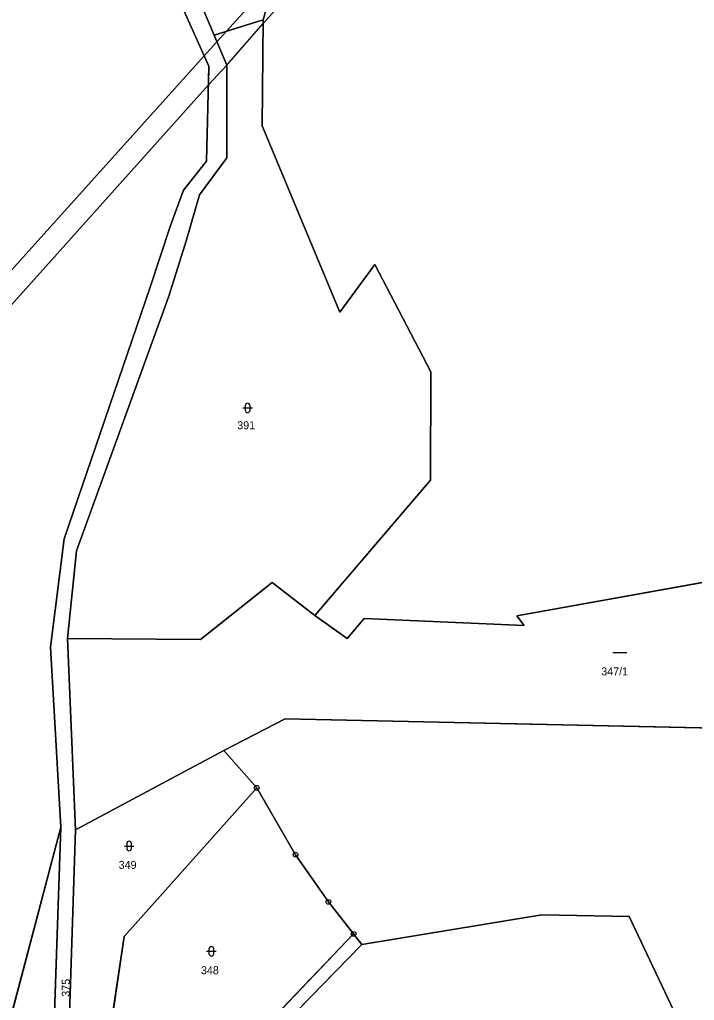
# Model space of a CAD drawing. Extents: x -689422 to -685210, y -987725 to -982160.
# Drawn here: x -686725.1 to -686581.7, y -987064.7 to -986856.4 of the extents above; entities that cross this region are included whole.
import ezdxf

# ---------------------------------------------------------------- set-up
doc = ezdxf.new("R2010")
doc.units = 0
for name, color, linetype in [('KN_Hranice_parcel', 7, 'Continuous'), ('KN_Parcelni cisla', 7, 'Continuous'), ('KN_Polygon parcely', 7, 'Continuous'), ('KN_POZEMKY_LESNI POZEMEK', 7, 'Continuous'), ('KN_POZEMKY_ORNA PUDA', 7, 'Continuous'), ('KN_POZEMKY_OSTATNI PLOCHA', 7, 'Continuous'), ('KN_POZEMKY_TTP', 7, 'Continuous'), ('KN_POZEMKY_VODNI_PLOCHA', 7, 'Continuous'), ('KN_VYUZITI_11_vodni plocha_zamokrena plocha', 7, 'Continuous'), ('KN_VYUZITI_27_ostatni plocha_neplodna puda', 7, 'Continuous'), ('KN_Věcná břemena k části', 7, 'Continuous'), ('KN_Značky bodu BP', 7, 'Continuous'), ('KN_Značky kultur', 7, 'Continuous')]:
    doc.layers.add(name, color=color, linetype=linetype)

msp = doc.modelspace()

# ---------------------------------------------------------------- linework, layer by layer
at = {"layer": 'KN_Hranice_parcel'}
for p, q in [((-686683.77, -986859.67), (-686687.52, -986850.74)), ((-686683.77, -986859.67), (-686673.32, -986856.41)), ((-686681.09, -986866.04), (-686683.77, -986859.67)), ((-686713.26, -987028.49), (-686714.94, -986987.85)), ((-686681.69, -987011.66), (-686713.26, -987028.49)), ((-686681.69, -987011.66), (-686674.7, -987019.58)), ((-686733.52, -987092.86), (-686716.4, -987027.91)), ((-686713.26, -987028.49), (-686714.49, -987067.68)), ((-686690.67, -987088.77), (-686654.13, -987050.63)), ((-686654.13, -987050.63), (-686652.37, -987052.87)), ((-686688.62, -987090), (-686652.37, -987052.87))]:
    msp.add_line(p, q, dxfattribs=at)
for points in [[(-686673.32, -986856.41), (-686666.27, -986831.41), (-686664.05, -986828.32)], [(-686691.17, -986852.38), (-686684.89, -986866.29), (-686685.39, -986886.42), (-686690.27, -986892.63), (-686693.02, -986900.13), (-686697.36, -986913.18), (-686715.65, -986966.67), (-686718.56, -986989.73), (-686716.4, -987027.91)], [(-686662.38, -986982.96), (-686637.77, -986954.19), (-686637.74, -986931.17), (-686649.58, -986908.38), (-686657.04, -986918.52), (-686673.53, -986878.97), (-686673.32, -986856.41)], [(-686714.94, -986987.85), (-686713.04, -986969.23), (-686693.39, -986915.11), (-686689.62, -986903.15), (-686686.9, -986893.59), (-686681.09, -986885.71), (-686681.09, -986866.04)], [(-686662.38, -986982.96), (-686655.5, -986987.84), (-686651.87, -986983.58), (-686617.9, -986985.1), (-686619.46, -986983.03), (-686557.32, -986971.9), (-686505.91, -986947.47)], [(-686504.67, -986950.08), (-686560.93, -987007.24), (-686668.7, -987004.92), (-686681.69, -987011.66)], [(-686714.94, -986987.85), (-686686.65, -986988.06), (-686671.44, -986975.93), (-686662.38, -986982.96)], [(-686674.7, -987019.58), (-686702.89, -987051.19), (-686706.43, -987074.82)], [(-686674.7, -987019.58), (-686666.47, -987033.78), (-686659.49, -987043.8), (-686654.13, -987050.63)], [(-686716.4, -987027.91), (-686717.94, -987073.53), (-686728.06, -987101.24)], [(-686652.37, -987052.87), (-686614.11, -987046.56), (-686595.53, -987046.88), (-686581.68, -987076.21)]]:
    msp.add_lwpolyline(points, dxfattribs=at)
at = {"layer": 'KN_Polygon parcely'}
for points in [[(-686733.52, -987092.86), (-686716.4, -987027.91), (-686718.56, -986989.73), (-686715.65, -986966.67), (-686697.36, -986913.18), (-686693.02, -986900.13), (-686690.27, -986892.63), (-686685.39, -986886.42), (-686684.89, -986866.29), (-686691.17, -986852.38), (-686681.76, -986829.17), (-686675.53, -986783.03), (-686669.76, -986751.7), (-686668.93, -986748.08), (-686678.49, -986747.97), (-686683.49, -986747.92), (-686683.45, -986743.82), (-686687.59, -986743.78), (-686689.2, -986743.77), (-686703.89, -986756.61), (-686709.75, -986769.81), (-686726.31, -986778.54)], [(-686666.27, -986831.41), (-686673.32, -986856.41), (-686673.53, -986878.97), (-686657.04, -986918.52), (-686649.58, -986908.38), (-686637.74, -986931.17), (-686637.77, -986954.19), (-686662.38, -986982.96), (-686655.5, -986987.84), (-686651.87, -986983.58), (-686617.9, -986985.1), (-686619.46, -986983.03), (-686557.32, -986971.9), (-686505.91, -986947.47), (-686469.15, -986930), (-686412.17, -986912.77), (-686386.41, -986874.65), (-686371.81, -986852.38)], [(-686691.17, -986852.38), (-686684.89, -986866.29), (-686685.39, -986886.42), (-686690.27, -986892.63), (-686693.02, -986900.13), (-686697.36, -986913.18), (-686715.65, -986966.67), (-686718.56, -986989.73), (-686716.4, -987027.91), (-686717.94, -987073.53)], [(-686714.49, -987067.68), (-686713.26, -987028.49), (-686714.94, -986987.85), (-686713.04, -986969.23), (-686693.39, -986915.11), (-686689.62, -986903.15), (-686686.9, -986893.59), (-686681.09, -986885.71), (-686681.09, -986866.04), (-686683.77, -986859.67), (-686687.52, -986850.74)]]:
    msp.add_lwpolyline(points, dxfattribs=at)
for points in [[(-686673.32, -986856.41), (-686666.27, -986831.41), (-686664.05, -986828.32), (-686667.8, -986817.71), (-686679.02, -986830.76), (-686687.52, -986850.74), (-686683.77, -986859.67)], [(-686637.74, -986931.17), (-686649.58, -986908.38), (-686657.04, -986918.52), (-686673.53, -986878.97), (-686673.32, -986856.41), (-686683.77, -986859.67), (-686681.09, -986866.04), (-686681.09, -986885.71), (-686686.9, -986893.59), (-686689.62, -986903.15), (-686693.39, -986915.11), (-686713.04, -986969.23), (-686714.94, -986987.85), (-686686.65, -986988.06), (-686671.44, -986975.93), (-686662.38, -986982.96), (-686637.77, -986954.19)], [(-686652.37, -987052.87), (-686614.11, -987046.56), (-686595.53, -987046.88), (-686581.68, -987076.21), (-686572.33, -987071.03), (-686546.33, -987062.48), (-686523.93, -987050.98), (-686517.25, -987045.2), (-686492.74, -987035.48), (-686491.96, -987039.41), (-686473.83, -987019.69), (-686459.48, -986999.8), (-686446.86, -986992.75), (-686438.2, -986975.26), (-686433.86, -986944.85), (-686451.29, -986938.63), (-686504.67, -986950.08), (-686560.93, -987007.24), (-686668.7, -987004.92), (-686681.69, -987011.66), (-686674.7, -987019.58), (-686666.47, -987033.78), (-686659.49, -987043.8), (-686654.13, -987050.63)], [(-686505.91, -986947.47), (-686557.32, -986971.9), (-686619.46, -986983.03), (-686617.9, -986985.1), (-686651.87, -986983.58), (-686655.5, -986987.84), (-686662.38, -986982.96), (-686671.44, -986975.93), (-686686.65, -986988.06), (-686714.94, -986987.85), (-686713.26, -987028.49), (-686681.69, -987011.66), (-686668.7, -987004.92), (-686560.93, -987007.24), (-686504.67, -986950.08)], [(-686713.26, -987028.49), (-686714.49, -987067.68), (-686706.43, -987074.82), (-686702.89, -987051.19), (-686674.7, -987019.58), (-686681.69, -987011.66)], [(-686702.89, -987051.19), (-686706.43, -987074.82), (-686690.67, -987088.77), (-686654.13, -987050.63), (-686659.49, -987043.8), (-686666.47, -987033.78), (-686674.7, -987019.58)], [(-686716.4, -987027.91), (-686733.52, -987092.86), (-686728.06, -987101.24), (-686717.94, -987073.53)], [(-686574.05, -987105.43), (-686575.15, -987097.93), (-686581.68, -987076.21), (-686595.53, -987046.88), (-686614.11, -987046.56), (-686652.37, -987052.87), (-686688.62, -987090), (-686617.02, -987138.1), (-686603.14, -987129.29)], [(-686688.62, -987090), (-686652.37, -987052.87), (-686654.13, -987050.63), (-686690.67, -987088.77)]]:
    msp.add_lwpolyline(points, close=True, dxfattribs=at)
at = {"layer": 'KN_POZEMKY_LESNI POZEMEK'}
for p, q in [((-686666.27, -986831.41), (-686673.32, -986856.41)), ((-686683.77, -986859.67), (-686687.52, -986850.74)), ((-686673.32, -986856.41), (-686683.77, -986859.67))]:
    msp.add_line(p, q, dxfattribs=at)
at = {"layer": 'KN_POZEMKY_ORNA PUDA'}
for p, q in [((-686673.32, -986856.41), (-686666.27, -986831.41)), ((-686673.53, -986878.97), (-686673.32, -986856.41)), ((-686657.04, -986918.52), (-686673.53, -986878.97)), ((-686649.58, -986908.38), (-686657.04, -986918.52)), ((-686637.74, -986931.17), (-686649.58, -986908.38)), ((-686637.77, -986954.19), (-686637.74, -986931.17)), ((-686662.38, -986982.96), (-686637.77, -986954.19)), ((-686557.32, -986971.9), (-686619.46, -986983.03)), ((-686655.5, -986987.84), (-686662.38, -986982.96)), ((-686651.87, -986983.58), (-686655.5, -986987.84)), ((-686617.9, -986985.1), (-686651.87, -986983.58)), ((-686619.46, -986983.03), (-686617.9, -986985.1))]:
    msp.add_line(p, q, dxfattribs=at)
at = {"layer": 'KN_POZEMKY_OSTATNI PLOCHA'}
for p, q in [((-686684.89, -986866.29), (-686691.17, -986852.38)), ((-686687.52, -986850.74), (-686683.77, -986859.67)), ((-686683.77, -986859.67), (-686673.32, -986856.41)), ((-686673.32, -986856.41), (-686673.53, -986878.97)), ((-686683.77, -986859.67), (-686681.09, -986866.04)), ((-686681.09, -986866.04), (-686683.77, -986859.67)), ((-686685.39, -986886.42), (-686684.89, -986866.29)), ((-686681.09, -986866.04), (-686681.09, -986885.71)), ((-686681.09, -986885.71), (-686681.09, -986866.04)), ((-686673.53, -986878.97), (-686657.04, -986918.52)), ((-686681.09, -986885.71), (-686686.9, -986893.59)), ((-686686.9, -986893.59), (-686681.09, -986885.71)), ((-686690.27, -986892.63), (-686685.39, -986886.42)), ((-686693.02, -986900.13), (-686690.27, -986892.63)), ((-686686.9, -986893.59), (-686689.62, -986903.15)), ((-686689.62, -986903.15), (-686686.9, -986893.59)), ((-686697.36, -986913.18), (-686693.02, -986900.13)), ((-686689.62, -986903.15), (-686693.39, -986915.11)), ((-686693.39, -986915.11), (-686689.62, -986903.15)), ((-686657.04, -986918.52), (-686649.58, -986908.38)), ((-686649.58, -986908.38), (-686637.74, -986931.17)), ((-686715.65, -986966.67), (-686697.36, -986913.18)), ((-686693.39, -986915.11), (-686713.04, -986969.23)), ((-686713.04, -986969.23), (-686693.39, -986915.11)), ((-686637.74, -986931.17), (-686637.77, -986954.19)), ((-686637.77, -986954.19), (-686662.38, -986982.96)), ((-686718.56, -986989.73), (-686715.65, -986966.67)), ((-686713.04, -986969.23), (-686714.94, -986987.85)), ((-686714.94, -986987.85), (-686713.04, -986969.23)), ((-686671.44, -986975.93), (-686686.65, -986988.06)), ((-686662.38, -986982.96), (-686671.44, -986975.93)), ((-686714.94, -986987.85), (-686713.26, -987028.49)), ((-686686.65, -986988.06), (-686714.94, -986987.85)), ((-686716.4, -987027.91), (-686718.56, -986989.73)), ((-686713.26, -987028.49), (-686681.69, -987011.66)), ((-686681.69, -987011.66), (-686674.7, -987019.58)), ((-686674.7, -987019.58), (-686702.89, -987051.19)), ((-686702.89, -987051.19), (-686674.7, -987019.58)), ((-686674.7, -987019.58), (-686666.47, -987033.78)), ((-686733.52, -987092.86), (-686716.4, -987027.91)), ((-686717.94, -987073.53), (-686716.4, -987027.91)), ((-686716.4, -987027.91), (-686717.94, -987073.53)), ((-686713.26, -987028.49), (-686714.49, -987067.68)), ((-686714.49, -987067.68), (-686713.26, -987028.49)), ((-686666.47, -987033.78), (-686659.49, -987043.8)), ((-686659.49, -987043.8), (-686654.13, -987050.63)), ((-686702.89, -987051.19), (-686706.43, -987074.82)), ((-686706.43, -987074.82), (-686702.89, -987051.19)), ((-686690.67, -987088.77), (-686654.13, -987050.63)), ((-686654.13, -987050.63), (-686690.67, -987088.77)), ((-686654.13, -987050.63), (-686652.37, -987052.87)), ((-686652.37, -987052.87), (-686688.62, -987090))]:
    msp.add_line(p, q, dxfattribs=at)
at = {"layer": 'KN_POZEMKY_TTP'}
for p, q in [((-686691.17, -986852.38), (-686684.89, -986866.29)), ((-686684.89, -986866.29), (-686685.39, -986886.42)), ((-686685.39, -986886.42), (-686690.27, -986892.63)), ((-686690.27, -986892.63), (-686693.02, -986900.13)), ((-686693.02, -986900.13), (-686697.36, -986913.18)), ((-686697.36, -986913.18), (-686715.65, -986966.67)), ((-686715.65, -986966.67), (-686718.56, -986989.73)), ((-686718.56, -986989.73), (-686716.4, -987027.91)), ((-686681.69, -987011.66), (-686668.7, -987004.92)), ((-686668.7, -987004.92), (-686560.93, -987007.24)), ((-686674.7, -987019.58), (-686681.69, -987011.66)), ((-686666.47, -987033.78), (-686674.7, -987019.58)), ((-686716.4, -987027.91), (-686733.52, -987092.86)), ((-686659.49, -987043.8), (-686666.47, -987033.78)), ((-686654.13, -987050.63), (-686659.49, -987043.8)), ((-686614.11, -987046.56), (-686652.37, -987052.87)), ((-686652.37, -987052.87), (-686614.11, -987046.56)), ((-686595.53, -987046.88), (-686614.11, -987046.56)), ((-686614.11, -987046.56), (-686595.53, -987046.88)), ((-686581.68, -987076.21), (-686595.53, -987046.88)), ((-686595.53, -987046.88), (-686581.68, -987076.21)), ((-686652.37, -987052.87), (-686654.13, -987050.63)), ((-686688.62, -987090), (-686652.37, -987052.87))]:
    msp.add_line(p, q, dxfattribs=at)
at = {"layer": 'KN_POZEMKY_VODNI_PLOCHA'}
for p, q in [((-686619.46, -986983.03), (-686557.32, -986971.9)), ((-686686.65, -986988.06), (-686671.44, -986975.93)), ((-686671.44, -986975.93), (-686662.38, -986982.96)), ((-686662.38, -986982.96), (-686655.5, -986987.84)), ((-686655.5, -986987.84), (-686651.87, -986983.58)), ((-686651.87, -986983.58), (-686617.9, -986985.1)), ((-686617.9, -986985.1), (-686619.46, -986983.03)), ((-686713.26, -987028.49), (-686714.94, -986987.85)), ((-686714.94, -986987.85), (-686686.65, -986988.06)), ((-686668.7, -987004.92), (-686681.69, -987011.66)), ((-686560.93, -987007.24), (-686668.7, -987004.92)), ((-686681.69, -987011.66), (-686713.26, -987028.49))]:
    msp.add_line(p, q, dxfattribs=at)
at = {"layer": 'KN_VYUZITI_11_vodni plocha_zamokrena plocha'}
for p, q in [((-686619.46, -986983.03), (-686557.32, -986971.9)), ((-686686.65, -986988.06), (-686671.44, -986975.93)), ((-686671.44, -986975.93), (-686662.38, -986982.96)), ((-686662.38, -986982.96), (-686655.5, -986987.84)), ((-686655.5, -986987.84), (-686651.87, -986983.58)), ((-686651.87, -986983.58), (-686617.9, -986985.1)), ((-686617.9, -986985.1), (-686619.46, -986983.03)), ((-686713.26, -987028.49), (-686714.94, -986987.85)), ((-686714.94, -986987.85), (-686686.65, -986988.06)), ((-686668.7, -987004.92), (-686681.69, -987011.66)), ((-686560.93, -987007.24), (-686668.7, -987004.92)), ((-686681.69, -987011.66), (-686713.26, -987028.49))]:
    msp.add_line(p, q, dxfattribs=at)
at = {"layer": 'KN_VYUZITI_27_ostatni plocha_neplodna puda'}
for p, q in [((-686684.89, -986866.29), (-686691.17, -986852.38)), ((-686687.52, -986850.74), (-686683.77, -986859.67)), ((-686683.77, -986859.67), (-686673.32, -986856.41)), ((-686673.32, -986856.41), (-686673.53, -986878.97)), ((-686683.77, -986859.67), (-686681.09, -986866.04)), ((-686681.09, -986866.04), (-686683.77, -986859.67)), ((-686685.39, -986886.42), (-686684.89, -986866.29)), ((-686681.09, -986866.04), (-686681.09, -986885.71)), ((-686681.09, -986885.71), (-686681.09, -986866.04)), ((-686673.53, -986878.97), (-686657.04, -986918.52)), ((-686681.09, -986885.71), (-686686.9, -986893.59)), ((-686686.9, -986893.59), (-686681.09, -986885.71)), ((-686690.27, -986892.63), (-686685.39, -986886.42)), ((-686693.02, -986900.13), (-686690.27, -986892.63)), ((-686686.9, -986893.59), (-686689.62, -986903.15)), ((-686689.62, -986903.15), (-686686.9, -986893.59)), ((-686697.36, -986913.18), (-686693.02, -986900.13)), ((-686689.62, -986903.15), (-686693.39, -986915.11)), ((-686693.39, -986915.11), (-686689.62, -986903.15)), ((-686657.04, -986918.52), (-686649.58, -986908.38)), ((-686649.58, -986908.38), (-686637.74, -986931.17)), ((-686715.65, -986966.67), (-686697.36, -986913.18)), ((-686693.39, -986915.11), (-686713.04, -986969.23)), ((-686713.04, -986969.23), (-686693.39, -986915.11)), ((-686637.74, -986931.17), (-686637.77, -986954.19)), ((-686637.77, -986954.19), (-686662.38, -986982.96)), ((-686718.56, -986989.73), (-686715.65, -986966.67)), ((-686713.04, -986969.23), (-686714.94, -986987.85)), ((-686714.94, -986987.85), (-686713.04, -986969.23)), ((-686671.44, -986975.93), (-686686.65, -986988.06)), ((-686662.38, -986982.96), (-686671.44, -986975.93)), ((-686714.94, -986987.85), (-686713.26, -987028.49)), ((-686686.65, -986988.06), (-686714.94, -986987.85)), ((-686716.4, -987027.91), (-686718.56, -986989.73)), ((-686713.26, -987028.49), (-686681.69, -987011.66)), ((-686681.69, -987011.66), (-686674.7, -987019.58)), ((-686674.7, -987019.58), (-686702.89, -987051.19)), ((-686702.89, -987051.19), (-686674.7, -987019.58)), ((-686674.7, -987019.58), (-686666.47, -987033.78)), ((-686733.52, -987092.86), (-686716.4, -987027.91)), ((-686717.94, -987073.53), (-686716.4, -987027.91)), ((-686716.4, -987027.91), (-686717.94, -987073.53)), ((-686713.26, -987028.49), (-686714.49, -987067.68)), ((-686714.49, -987067.68), (-686713.26, -987028.49)), ((-686666.47, -987033.78), (-686659.49, -987043.8)), ((-686659.49, -987043.8), (-686654.13, -987050.63)), ((-686702.89, -987051.19), (-686706.43, -987074.82)), ((-686706.43, -987074.82), (-686702.89, -987051.19)), ((-686690.67, -987088.77), (-686654.13, -987050.63)), ((-686654.13, -987050.63), (-686690.67, -987088.77)), ((-686654.13, -987050.63), (-686652.37, -987052.87)), ((-686652.37, -987052.87), (-686688.62, -987090))]:
    msp.add_line(p, q, dxfattribs=at)
at = {"layer": 'KN_Věcná břemena k části'}
for points in [[(-686670.75, -986847.31), (-686673.32, -986856.41), (-686673.33, -986857.22), (-686650.17, -986831.4), (-686650.29, -986831.29), (-686643.2, -986823.41), (-686643.09, -986823.51), (-686641.4, -986821.63), (-686644.86, -986818.57)], [(-686670.75, -986847.31), (-686681.15, -986858.85), (-686673.32, -986856.41)], [(-686685.88, -986864.1), (-686684.89, -986866.29), (-686684.99, -986870.22), (-686681.09, -986866.04), (-686673.33, -986857.22), (-686673.32, -986856.41), (-686681.15, -986858.85), (-686683.17, -986861.1)], [(-686809.41, -987001.23), (-686809.04, -987002.95), (-686808.18, -987007), (-686756.99, -986950.45), (-686757.19, -986950.27), (-686752.04, -986944.55), (-686751.83, -986944.74), (-686684.99, -986870.22), (-686684.89, -986866.29), (-686685.88, -986864.1), (-686757.9, -986944.04)]]:
    msp.add_lwpolyline(points, close=True, dxfattribs=at)
at = {"layer": 'KN_Značky bodu BP'}
for centre, radius in [((-686674.7, -987019.58), 0.5), ((-686674.7, -987019.58), 0.0303), ((-686666.47, -987033.78), 0.5), ((-686666.47, -987033.78), 0.0303), ((-686659.49, -987043.8), 0.5), ((-686659.49, -987043.8), 0.0303), ((-686654.13, -987050.63), 0.5), ((-686654.13, -987050.63), 0.0303)]:
    msp.add_circle(centre, radius, dxfattribs=at)
at = {"layer": 'KN_Značky kultur'}
for p, q in [((-686677.65, -986938.88), (-686675.65, -986938.88)), ((-686677.15, -986938.38), (-686677.15, -986939.38)), ((-686676.15, -986939.38), (-686676.15, -986938.38)), ((-686599.01, -986990.81), (-686596.01, -986990.81)), ((-686702.35, -987031.44), (-686702.35, -987032.44)), ((-686701.35, -987032.44), (-686701.35, -987031.44)), ((-686702.85, -987031.94), (-686700.85, -987031.94)), ((-686685.37, -987054.31), (-686683.37, -987054.31)), ((-686684.87, -987053.81), (-686684.87, -987054.81)), ((-686683.87, -987054.81), (-686683.87, -987053.81))]:
    msp.add_line(p, q, dxfattribs=at)
for centre, start, end in [((-686676.65, -986938.38), 0, 180), ((-686676.65, -986939.38), 180, 359.9879), ((-686701.85, -987031.44), 0, 180), ((-686701.85, -987032.44), 180, 359.9879), ((-686684.37, -987053.81), 0, 180), ((-686684.37, -987054.81), 180, 359.9879)]:
    msp.add_arc(centre, 0.5, start, end, dxfattribs=at)

# ---------------------------------------------------------------- texts
at = {"layer": 'KN_Parcelni cisla'}
for s, p in [('391', (-686678.86, -986943.4)), ('347/1', (-686601.48, -986995.69)), ('349', (-686704.07, -987036.79)), ('348', (-686686.58, -987059.18))]:
    msp.add_text(s, height=1.7, dxfattribs=at).set_placement(p)
msp.add_text('375', height=1.7, rotation=90, dxfattribs=at).set_placement((-686714.46, -987063.96))

doc.saveas('drawing.dxf')
